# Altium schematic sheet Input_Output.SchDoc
size A; SheetNumber: 2; SheetTotal: 5
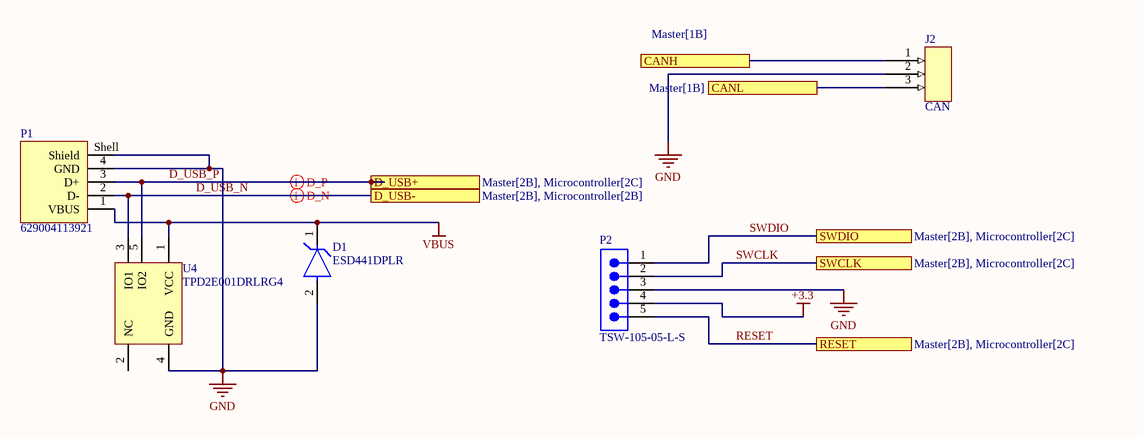
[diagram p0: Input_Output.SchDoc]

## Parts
D1  ESD441DPLR  [FP-DPL0002A-MFG]
J2  CAN  [3 pin 2.54mm header-Footprint-1]
P1  629004113921  [629004113921]
P2  TSW-105-05-L-S  [SMTC-TSW-105-05-X-S]
U4  TPD2E001DRLRG4  [DRL0005A_L]

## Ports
CANH (see Master[1B]), CANL (see Master[1B]), D_USB+ (see Master[2B], Microcontroller[2C]), D_USB- (see Master[2B], Microcontroller[2B]), RESET (see Master[2B], Microcontroller[2C]), SWCLK (see Master[2B], Microcontroller[2C]), SWDIO (see Master[2B], Microcontroller[2C])

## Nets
+3.3: P2.4
GND: D1.2(GND) J2.2 P1.4(GND) P1.Shell(Shield) P2.3 U4.4(GND)
VBUS: D1.1(IO) P1.1(VBUS) U4.1(VCC)
CANH: J2.1 ; port CANH
CANL: J2.3 ; port CANL
D_USB_N: P1.2(D-) U4.3(IO1) ; port D_USB-
D_USB_P: P1.3(D+) U4.5(IO2) ; port D_USB+
RESET: P2.5 ; port RESET
SWCLK: P2.2 ; port SWCLK
SWDIO: P2.1 ; port SWDIO

Not connected (* = marked no-connect by the designer): U4 2(NC)

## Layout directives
differential pair: D_USB_N, D_USB_P

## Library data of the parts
D1 = CMP-00370-140306675-1: ESD441DPLR 1-pF, 5.5-V, 30-KV ESD protection device in 0201 package 2-X2SON -40 to 125; Manufacturer Lifecycle Status: ACTIVE; Number of Channels: 1; Breakdown Voltage: 6V; Capacitance: 1pF; Peak Pulse Current: 6A; Direction: Unidirectional; Peak Pulse Power: 45W; Reverse Standoff Voltage: 5.5V; Clamping Voltage: 3.8V
J2 = CMP-002-00074-2: 3 pin header for jumpers connectors 2.54mm pitch.
P1 = CMP-1502-03242-2: NexarPartId: 19991169; USB Standard: USB 2.0; Gender: Male; Connector Type: USB; Contact Resistance: 20mΩ; Current Rating: 1.5A; Number of Contacts: 4; Insulation Resistance: 1GΩ; Operating Supply Voltage: 30V
P2 = CMP-1024-00366-1: 0.025" SQ Post Header, Through-hole, Vertical, -55 to 125 degC, 2.54 mm Pitch, 5-Pin, Male, RoHS; Manufacturer: Samtec; Pitch: 2.54 mm
U4 = CMP-0326-00050-2: Low-Capacitance + / - 15 kV ESD-Protection Array for High-Speed Data Interfaces, 2 Channels, -40 to +85 degC, 5-pin SOT (DRL), Green (RoHS & no Sb/Br); Manufacturer: Texas Instruments; USB High Speed: TRUE; IO Leakage Current(nA): 1; IEC 61000-4-2 Contact(+/- kV): 8; Breakdown Voltage(Min)(V): 11; IEC 61000-4-2 Air-Gap(+/- kV): 15; IO Capacitance(Typ)(pF): 1.5; SubFamily: ESD Solution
